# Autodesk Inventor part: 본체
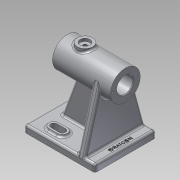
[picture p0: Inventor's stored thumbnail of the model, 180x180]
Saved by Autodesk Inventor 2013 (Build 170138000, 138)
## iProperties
Created: 2019-10
Part Number: 본체
Material: 알루미늄 6061
Document SubType Name: Modeling
Designer: Administrator
Density: 2.71 g/cm^3
Mass: 575.016 g
Surface Area: 532.495 cm^2
Volume: 212.183 cm^3
Author: Administrator
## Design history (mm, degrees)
sketch "스케치1"
  geometry: C1 r 21 at (0, 0); 1 further point
  constraints: 1 centre point, 1 coincident
  dimensions: "d0" = 42 diameter of C1
extrude "돌출1" new body sketch "스케치1" stored distance "d1" = 82; taper "d2" = 0 deg
hole "구멍1" diameter "d5" = 23; stored, may be unused: countersink angle "d9" = 90 deg, drill point angle "d11" = 118 deg; dims "d3" = 10, "d4" = 10, "d6" = 6, "d7" = 29, "d8" = 62, "d10" = 8
sketch "스케치2"
  geometry: C1 r 14.5 at (0, 0) reference; 1 further point
  constraints: 1 vertical alignment
  dimensions: "d12" = 18 distance of C1.centre point (0, 18)
hole "구멍2" sketch "스케치2" at (0, 18) diameter "d13" = 2.459; stored, may be unused: countersink angle "d17" = 90 deg, drill point angle "d19" = 118 deg; dims "d14" = 8, "d15" = 29, "d16" = 62, "d18" = 10
node "작업 평면1"
sketch "스케치3"
  geometry: L1 (21, 41)-(-21, 41) reference; C1 r 11 at (0, 16); 1 further point
  constraints: 1 centre point, 1 vertical alignment
  dimensions: "d24" = 25 distance from line of L1 C1.centre; "d25" = 22 diameter of C1
extrude "돌출2" join sketch "스케치3" stored distance "d26" = 82; taper "d27" = 0 deg
sketch "스케치4"
  geometry: C1 r 11 at (0, 0) reference; C2 r 7 at (0, 0); 1 further point
  constraints: 1 centre point, 1 coincident
  dimensions: "d28" = 14 diameter of C2
extrude "돌출3" cut sketch "스케치4" distance "d30" = 4; taper "d31" = 0 deg
hole "구멍3" diameter "d34" = 4.917; stored, may be unused: countersink angle "d38" = 90 deg, drill point angle "d40" = 0 deg; dims "d32" = 10, "d33" = 10, "d35" = 8, "d36" = 29, "d37" = 62, "d39" = 10
sketch "스케치5"
  geometry: L1 (-76, -41)-(-86, -41); L2 (-86, -41)-(-86, 59); L3 (-86, 59)-(-76, 59); L4 (-76, 59)-(-76, -41); L5 (-21, -41)-(21, -41) reference; 1 further point
  constraints: 8 end point, 2 parallel, 1 collinear, 1 horizontal, 1 perpendicular
  dimensions: "d41" = 100 distance of L1.end L2.end; "d43" = 10 distance of L1.start L1.end; "d44" = 86 distance from line of point (0, 0) L2
extrude "돌출4" join sketch "스케치5" stored distance "d45" = 86; taper "d46" = 0 deg
sketch "스케치6"
  geometry: L1 (86, 0)-(0, 0) reference; L2 (86, 100)-(86, 0) reference; L3 (9, 26)-(9, 38); L4 (23, 26)-(23, 38); L5 (11.5, 26)-(11.5, 38); L6 (20.5, 26)-(20.5, 38); A1 r 7 centre (16, 26) between (9, 26) and (23, 26); A2 r 7 centre (16, 38) between (23, 38) and (9, 38); A3 r 4.5 centre (16, 26) between (11.5, 26) and (20.5, 26); A4 r 4.5 centre (16, 38) between (20.5, 38) and (11.5, 38); 1 further point
  constraints: 8 end point, 8 point on circle, 7 tangent, 4 centre point, 2 coincident, 2 equal radius, 1 parallel, 1 vertical alignment
  dimensions: "d49" = 12 distance of L3.start L3.end; "d50" = 14 distance between parallel lines of L4 L3; "d51" = 27 horizontal distance of point (43, 59) A2.centre; "d52" = 26 distance from line of L1 A1.centre; "d53" = 9 distance between parallel lines of L6 L5
extrude "돌출5" join sketch "스케치6" distance "d54" = 3; taper "d55" = 0 deg
sketch "스케치7"
  geometry: L1 (-4.5, 12)-(-4.5, 0) reference; L2 (4.5, 0)-(4.5, 12) reference; A1 r 4.5 centre (0, 0) between (-4.5, 0) and (4.5, 0) reference; A2 r 4.5 centre (0, 12) between (4.5, 12) and (-4.5, 12) reference; 1 further point
extrude "돌출6" cut sketch "스케치7" stored distance "d56" = 3; taper "d57" = 0 deg
node "작업 평면2"
fillet "모깎기7" dims "d84" = 3
fillet "모깎기8" dims "d85" = 3
node "작업 평면3"
sketch "스케치14"
  geometry: L1 (-20.272, 5.48)-(-42.896, -78.217); L2 (20.272, 5.48)-(42.896, -78.217); L3 (-40, -76)-(40, -76) reference; A1 r 21 centre (0, 0) between (-20.272, 5.48) and (20.272, 5.48) reference; A2 r 3 centre (-40, -79) between (-40, -76) and (-43, -79) reference; A3 r 3 centre (40, -79) between (43, -79) and (40, -76) reference; 1 further point
  constraints: 4 end point, 4 point on circle, 4 tangent
extrude "돌출8" join sketch "스케치14" distance "d87" = 10; taper "d88" = 0 deg
sketch "스케치15"
  geometry: L1 (-76, 56)-(-76, -38) reference; L2 (-76, 44)-(-65.7, 40.251); L3 (-86, 59)-(-79, 59) reference; 2 further points
  constraints: 2 end point, 1 point on line
  dimensions: "d89" = 70 deg angle of L1 L2; "d90" = 15 distance from line of L3 L2.start
feature "리브2" sketch "스케치15" dims "d91" = 1, "d92" = 10, "d93" = 0, "d94" = 0, "d95" = 1, "d96" = 1
sketch "스케치16"
  geometry: L1 (80, 3)-(0, 3) reference; 4 further points
  constraints: 1 vertical alignment, 1 other
  dimensions: "d99" = 7 distance from line of L1 point (40, -4)
feature "엠보싱2" sketch "스케치16" dims "d100" = 0.5, "d101" = 0
fillet "모깎기11" dims "d102" = 3
fillet "모깎기12" dims "d103" = 3
chamfer "모따기2" distance "d104" = 1; stored, may be unused: second distance "d105" = 2, angle "d106" = 45 deg
node "솔리드1"
pattern_circular "원형 패턴1" dims angle "d21" = 360 deg
mirror "대칭1"
mirror "대칭2"
other parameters: "d23" = 24, "d60" = -26, "d86" = -26
